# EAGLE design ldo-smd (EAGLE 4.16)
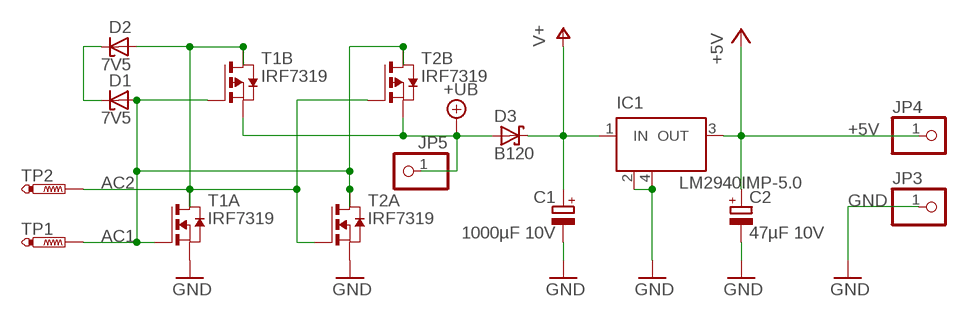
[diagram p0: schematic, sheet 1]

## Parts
C1  1000µF 10V  CPOL-EUTT5D11L  [TT5D11L]
C2  47µF 10V  CPOL-EUCT6032  [CT6032]
D1  7V5  ZENER-DIODESOD80C  [SOD80C]
D2  7V5  ZENER-DIODESOD80C  [SOD80C]
D3  B120  SCHOTTKY-DIODESMD  [SMB]
IC1  LM2940IMP-5.0  LM340S  [SOT223]
JP3  PINHD-1X1  [1X01]
JP4  PINHD-1X1  [1X01]
JP5  PINHD-1X1  [1X01]
T1  IRF7319  PN_MOSFET-SO8  [SO8]
T2  IRF7319  PN_MOSFET-SO8  [SO8]
TP1  PTR1PAD1-13  [P1-13]
TP2  PTR1PAD1-13  [P1-13]

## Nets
+5V: C2.+ IC1.3(OUT) JP4.1
+UB: D3.A JP5.1 T1.3(B:S) T2.3(B:S)
AC: D1.C D2.C
AC1: D1.A T1.2(A:G) T1.4(B:G) T2.5(B:D) T2.6(B:D2) T2.7(A:D) T2.8(A:D2) TP1.1(TP)
AC2: D2.A T1.5(B:D) T1.6(B:D2) T1.7(A:D) T1.8(A:D2) T2.2(A:G) T2.4(B:G) TP2.1(TP)
GND: C1.- C2.- IC1.2(GND) IC1.4(GND) JP3.1 T1.1(A:S) T2.1(A:S)
V+: C1.+ D3.C IC1.1(IN)

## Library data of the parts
C1 C2 = rcl:CPOL-EU: POLARIZED CAPACITOR, European symbol
D1 D2 = diode:ZENER-DIODE: Z-Diode
D3 = diode:SCHOTTKY-DIODE: Schottky Diode
IC1 = linear:LM340S: 3-Terminal Positive Regulators Source: http://cache.national.com/ds/LM/LM340.pdf
JP3-JP5 = pinhead:PINHD-1X1: PIN HEADER
T1 T2 = zetex:PN_MOSFET-: DUAL N AND P-CHANNEL ENHANCEMENT MODE MOSFET source ZXMD63C02.pdf from http://www.zetex.com/
TP1 TP2 = testpad:PTR1: TEST PIN

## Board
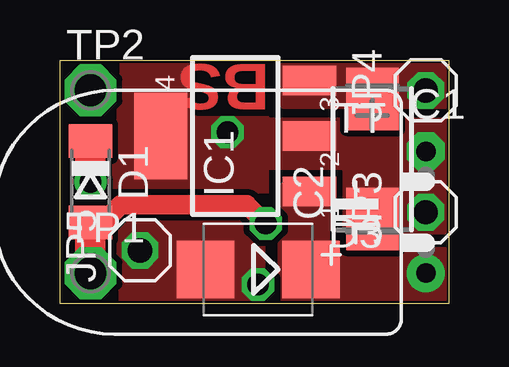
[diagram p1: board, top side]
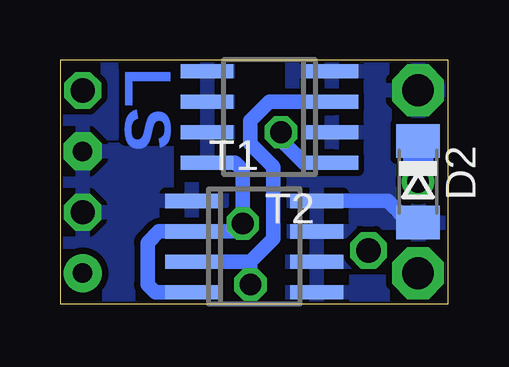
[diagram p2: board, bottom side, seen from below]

Size 16.18 x 10.15 mm. Coordinates in mm from the lower left corner, seen from the top.
Outline: 0,0 0,10.15 16.18,10.15 16.18,0 0,0
Copper layers (1*16): Top 0.035mm / dielectric 1.5mm / Bottom 0.035mm
Design rules "10mils": minimum track width 10mil, minimum drill 24mil, track to track 10mil, track to pad 10mil, pad to pad 10mil, via to via 10mil, smd to smd 10mil, copper to edge 4mil, drill to drill 1mil, minimum pad ring 10mil, minimum via ring 8mil, stop-mask expansion 0mil, vias tented up to drill 0mil, thermal gap 10mil

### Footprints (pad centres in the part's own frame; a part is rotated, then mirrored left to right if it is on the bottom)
TT5D11L = drill 0.813 pad 1.6 round: + -2.54,0 | drill 0.813 pad 1.6 octagon: - 2.54,0
CT6032 = smd 2.6 x 2.2: + 2.5,0; - -2.5,0
SOD80C = smd 1.4 x 1.8: A 1.7,0; C -1.7,0
SMB = smd 2.4 x 2.4: A 2.2,0; C -2.2,0
SOT223 = smd 1.219 x 2.235: 1 -2.311,-3.099; 2 0,-3.099; 3 2.311,-3.099 | smd 3.6 x 2.2: 4 0,3.099
1X01 = drill 1.016 octagon: 1 0,0
SO8 = smd 0.6 x 2.2: 1 -1.905,-2.6; 2 -0.635,-2.6; 3 0.635,-2.6; 4 1.905,-2.6; 5 1.905,2.6; 6 0.635,2.6; 7 -0.635,2.6; 8 -1.905,2.6
P1-13 = drill 1.321 pad 2.159 octagon: 1 0,0

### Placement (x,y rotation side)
C1  15.24,3.8 90 top
C2  13.01,6.03 90 top
D1  1.27,5.07 270 top
D2  1.27,5.07 270 bottom
D3  8.25,1.42 180 top
IC1  7.3,6.98 90 top
JP3  15.24,3.8 90 top
JP4  15.24,8.88 90 top
JP5  3.33,2.22 90 top
T1  8.09,2.38 270 bottom
T2  7.46,7.77 90 bottom
TP1  1.27,1.26 0 top
TP2  1.27,8.88 0 top

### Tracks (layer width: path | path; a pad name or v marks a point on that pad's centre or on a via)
+5V
  pour Top (no thermals): 16.19,10.15 9.36,10.15 9.36,8.41 16.19,8.41
+UB  (via drill 0.9)
  Bottom 0.61: v8.25,0.79 | v8.25,0.79 | 8.25,1.74 T1.3 | v8.25,0.79 8.25,1.74 | T2.3 7.46,8.41 8.25,7.61 8.25,6.66 7.3,5.71 7.3,2.69 8.25,1.74
  pour Top (no thermals): 0,-0.01 8.25,-0.01 8.25,3.65 0,3.65
AC  (via drill 0.9)
  Top 1.27: D1.C v1.27,5.07
  Bottom 1.27: v1.27,5.07 D1.C
AC1  (via drill 0.9)
  Top 0.813: D1.A 1.79,3.37 2.54,4.12 7.77,4.12 v8.57,3.33
  Top 1.27: D1.A | TP1.1 | TP1.1 D1.A
  Bottom 0.61: T1.4 12.22,0.47 12.54,0.79 12.54,2.53 12.06,3.01 T1.2 8.89,3.01 v8.57,3.33 8.57,5.55 8.89,5.87 T2.8
  pour Bottom: 9.2,5.87 9.2,10.15 10.63,10.15 10.63,5.87
AC2
  Bottom 0.61: D2.A 1.63,3.37 2.54,4.28 T1.8
  pour Bottom: -0.01,-0.01 -0.01,10.15 6.5,10.15 6.5,-0.01
GND  (via drill 0.9)
  Top 0.61: C2.- 13.33,3.53
  Bottom 0.61: v6.98,7.14 6.98,6.82 6.03,5.87 T2.1
  pour Top (no thermals): -0.01,4.6 -0.01,10.15 8.41,10.15 8.41,7.46 16.19,7.46 16.19,3.17 12.06,3.17 12.06,5.87 8.41,5.87 8.41,4.6
  pour Bottom: 9.04,-0.01 9.04,4.76 11.74,4.76 11.74,10.15 16.19,10.15 16.19,-0.01
V+
  pour Top (no thermals): 9.36,-0.01 16.19,-0.01 16.19,2.06 10.95,2.06 10.95,4.76 9.36,4.76

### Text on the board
Top: BS
Bottom: LS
